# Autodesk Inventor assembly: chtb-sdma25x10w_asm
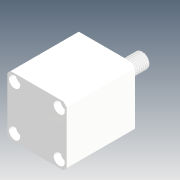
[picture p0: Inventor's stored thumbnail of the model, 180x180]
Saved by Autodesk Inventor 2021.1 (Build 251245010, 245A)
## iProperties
Company: Microsoft
Created: 2018-05
Part Number: chtb-sdma25x10w_asm
Description: STEP AP214
Document SubType Name: Assembly
Designer: user
Title: chtb-sdma25x10w_asm.STEP
Author: Windows
Revision Number: ÈÎºÎ
Sending System: SolidWorks 2015
Preprocessor: SwSTEP 2.0
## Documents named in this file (4)
- D:\Vault_2016\Projekty\Clamptek\Hydraulic\CHTB\CHTB-25\Inventor\chtb-sdma25x10w\chtb-sdma25x10w_asm.iam
- D:\Vault_2016\Projekty\Clamptek\Hydraulic\CHTB\CHTB-25\Inventor\chtb-sdma25x10w\CHTB-25QG.ipt
- D:\Vault_2016\Projekty\Clamptek\Hydraulic\CHTB\CHTB-25\Inventor\chtb-sdma25x10w\CHTB-SDMA25X10NBT.ipt
- D:\Vault_2016\Projekty\Clamptek\Hydraulic\CHTB\CHTB-25\Inventor\chtb-sdma25x10w\CHTB-SDMA25X10WHSG.ipt
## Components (3 placed, 3 different names)
1. CHTB-25QG_1
2. CHTB-SDMA25X10NBT_2
3. CHTB-SDMA25X10WHSG_3
